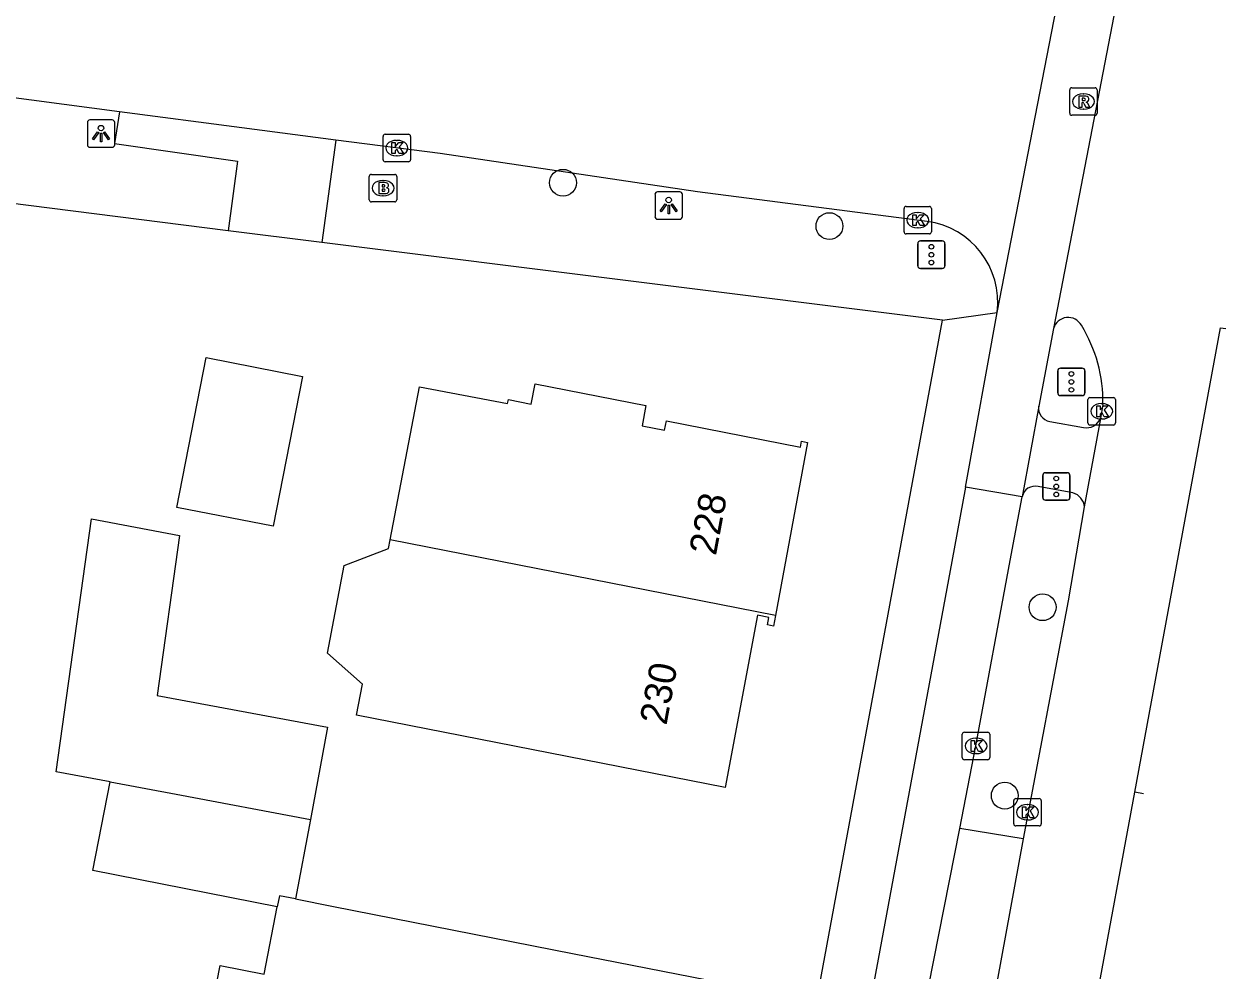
# Model space of a CAD drawing. Extents: x 161258 to 161838, y 380836 to 381727.
# Drawn here: x 161735.93 to 161779.71, y 381300.13 to 381334.61 of the extents above; entities that cross this region are included whole.
import ezdxf

# ---------------------------------------------------------------- set-up
doc = ezdxf.new("R2010")
doc.units = 0
for name, color, linetype in [('IMGEO_Boom', 7, 'Continuous'), ('IMGEO_Brandkraan', 7, 'Continuous'), ('IMGEO_Fietspad_gesloten', 7, 'Continuous'), ('IMGEO_Fietspad_open', 7, 'Continuous'), ('IMGEO_Kolk', 7, 'Continuous'), ('IMGEO_Lichtpunt', 7, 'Continuous'), ('IMGEO_OVBaan_gesloten', 7, 'Continuous'), ('IMGEO_Pand', 7, 'Continuous'), ('IMGEO_Pand_nummerreeks', 7, 'Continuous'), ('IMGEO_Rijbaan_lokaal_open', 7, 'Continuous'), ('IMGEO_Rijbaan_regionaal_gesloten', 7, 'Continuous'), ('IMGEO_Rioolput', 7, 'Continuous'), ('IMGEO_Verkeersregelinstallatiepaal', 7, 'Continuous'), ('IMGEO_Voetpad_open', 7, 'Continuous')]:
    doc.layers.add(name, color=color, linetype=linetype)

msp = doc.modelspace()

# ---------------------------------------------------------------- linework, layer by layer
at = {"layer": 'IMGEO_Boom'}
for centre in [(161755.562, 381328.829), (161765.266, 381327.249), (161773.031, 381313.372), (161771.653, 381306.512)]:
    msp.add_circle(centre, 0.489, dxfattribs=at)
at = {"layer": 'IMGEO_Brandkraan'}
for p, q in [((161748.506, 381328.208), (161748.506, 381329.06)), ((161748.581, 381329.134), (161749.433, 381329.134)), ((161748.994, 381328.914), (161749.019, 381328.914)), ((161749.507, 381329.06), (161749.507, 381328.208)), ((161749.017, 381328.354), (161748.992, 381328.354)), ((161749.433, 381328.134), (161748.581, 381328.134))]:
    msp.add_line(p, q, dxfattribs=at)
for points in [[(161748.506, 381328.208), (161748.506, 381329.06)], [(161748.581, 381329.134), (161749.433, 381329.134)], [(161748.854, 381328.834), (161748.854, 381328.434), (161749.067, 381328.434)], [(161749.085, 381328.834), (161748.854, 381328.834)], [(161749.507, 381329.06), (161749.507, 381328.208)], [(161749.033, 381328.753), (161748.979, 381328.753), (161748.979, 381328.677)], [(161748.979, 381328.677), (161749.032, 381328.677)], [(161749.041, 381328.601), (161748.979, 381328.601), (161748.979, 381328.52)], [(161748.979, 381328.52), (161749.041, 381328.52)], [(161749.433, 381328.134), (161748.581, 381328.134)]]:
    msp.add_lwpolyline(points, dxfattribs=at)
for centre, radius, start, end in [((161748.583, 381329.058), 0.0765, 91.552, 178.448), ((161748.583, 381329.058), 0.0765, 91.552, 178.448), ((161749.089, 381328.689), 0.145, 59.4692, 91.5367), ((161749.114, 381328.736), 0.0922, 285.5137, 58.1501), ((161749.431, 381329.058), 0.0765, 1.552, 88.448), ((161749.431, 381329.058), 0.0765, 1.552, 88.448), ((161749.034, 381328.715), 0.0379, 267.8285, 90.9355), ((161749.042, 381328.56), 0.0404, 269.8759, 90.5077), ((161749.073, 381328.685), 0.251, 268.6676, 293.5347), ((161749.119, 381328.544), 0.105, 301.3115, 78.989), ((161748.583, 381328.21), 0.0765, 181.552, 268.448), ((161748.583, 381328.21), 0.0765, 181.552, 268.448), ((161749.431, 381328.21), 0.0765, 271.552, 358.448), ((161749.431, 381328.21), 0.0765, 271.552, 358.448)]:
    msp.add_arc(centre, radius, start, end, dxfattribs=at)
for centre, major_axis, ratio, start_param, end_param in [((161748.993, 381328.634), (-0.387, 0.002), 0.722429, 4.712389, 7.853982), ((161749.018, 381328.634), (-0.39, 0.002), 0.717154, 1.570796, 4.712389)]:
    msp.add_ellipse(centre, major_axis=major_axis, ratio=ratio, start_param=start_param, end_param=end_param, dxfattribs=at)
at = {"layer": 'IMGEO_Fietspad_gesloten'}
for points in [[(161770.217, 381317.745), (161771.375, 381324.109)], [(161773.43, 381323.525), (161772.887, 381320.696)], [(161772.887, 381320.696), (161772.289, 381317.394)], [(161772.289, 381317.394), (161770.217, 381317.745)]]:
    msp.add_lwpolyline(points, dxfattribs=at)
at = {"layer": 'IMGEO_Fietspad_open'}
for points in [[(161770.217, 381317.745), (161769.724, 381315.032), (161762.12, 381274.018), (161757.67, 381250), (161756.52, 381243.79), (161755.513, 381238.354), (161742.385, 381167.493), (161739.245, 381150.478)], [(161770.018, 381305.316), (161770.601, 381308.32), (161771.852, 381315.075), (161772.289, 381317.394)]]:
    msp.add_lwpolyline(points, dxfattribs=at)
at = {"layer": 'IMGEO_Kolk'}
for p, q in [((161749.007, 381329.667), (161749.007, 381330.519)), ((161749.082, 381330.593), (161749.934, 381330.593)), ((161750.008, 381330.519), (161750.008, 381329.667)), ((161749.495, 381330.373), (161749.52, 381330.373)), ((161749.518, 381329.813), (161749.493, 381329.813)), ((161749.934, 381329.593), (161749.082, 381329.593)), ((161767.982, 381327.041), (161767.982, 381327.893)), ((161768.057, 381327.967), (161768.909, 381327.967)), ((161768.983, 381327.893), (161768.983, 381327.041)), ((161768.47, 381327.747), (161768.495, 381327.747)), ((161768.493, 381327.187), (161768.468, 381327.187)), ((161768.909, 381326.967), (161768.057, 381326.967)), ((161774.681, 381320.081), (161774.681, 381320.933)), ((161774.756, 381321.007), (161775.608, 381321.007)), ((161775.682, 381320.933), (161775.682, 381320.081)), ((161775.169, 381320.787), (161775.194, 381320.787)), ((161775.192, 381320.227), (161775.167, 381320.227)), ((161775.608, 381320.007), (161774.756, 381320.007)), ((161770.105, 381307.894), (161770.105, 381308.746)), ((161770.18, 381308.82), (161771.032, 381308.82)), ((161771.106, 381308.746), (161771.106, 381307.894)), ((161770.593, 381308.6), (161770.618, 381308.6)), ((161771.032, 381307.82), (161770.18, 381307.82)), ((161770.616, 381308.04), (161770.591, 381308.04)), ((161771.98, 381305.48), (161771.98, 381306.332)), ((161772.055, 381306.406), (161772.907, 381306.406)), ((161772.468, 381306.186), (161772.493, 381306.186)), ((161772.981, 381306.332), (161772.981, 381305.48)), ((161772.491, 381305.626), (161772.466, 381305.626)), ((161772.907, 381305.406), (161772.055, 381305.406))]:
    msp.add_line(p, q, dxfattribs=at)
for points in [[(161749.007, 381329.667), (161749.007, 381330.519)], [(161749.082, 381330.593), (161749.934, 381330.593)], [(161750.008, 381330.519), (161750.008, 381329.667)], [(161749.328, 381330.293), (161749.451, 381330.293), (161749.451, 381330.142), (161749.581, 381330.293), (161749.745, 381330.293), (161749.599, 381330.142), (161749.752, 381329.893), (161749.6, 381329.893), (161749.515, 381330.057), (161749.451, 381329.99), (161749.451, 381329.893), (161749.328, 381329.893), (161749.328, 381330.293)], [(161749.934, 381329.593), (161749.082, 381329.593)], [(161767.982, 381327.041), (161767.982, 381327.893)], [(161768.057, 381327.967), (161768.909, 381327.967)], [(161768.983, 381327.893), (161768.983, 381327.041)], [(161768.303, 381327.667), (161768.426, 381327.667), (161768.426, 381327.516), (161768.556, 381327.667), (161768.72, 381327.667), (161768.574, 381327.516), (161768.727, 381327.267), (161768.575, 381327.267), (161768.49, 381327.431), (161768.426, 381327.364), (161768.426, 381327.267), (161768.303, 381327.267), (161768.303, 381327.667)], [(161768.909, 381326.967), (161768.057, 381326.967)], [(161774.681, 381320.081), (161774.681, 381320.933)], [(161774.756, 381321.007), (161775.608, 381321.007)], [(161775.682, 381320.933), (161775.682, 381320.081)], [(161775.002, 381320.707), (161775.125, 381320.707), (161775.125, 381320.556), (161775.255, 381320.707), (161775.419, 381320.707), (161775.273, 381320.556), (161775.426, 381320.307), (161775.274, 381320.307), (161775.189, 381320.471), (161775.125, 381320.404), (161775.125, 381320.307), (161775.002, 381320.307), (161775.002, 381320.707)], [(161775.608, 381320.007), (161774.756, 381320.007)], [(161770.105, 381307.894), (161770.105, 381308.746)], [(161770.18, 381308.82), (161771.032, 381308.82)], [(161771.106, 381308.746), (161771.106, 381307.894)], [(161770.426, 381308.52), (161770.549, 381308.52), (161770.549, 381308.369), (161770.679, 381308.52), (161770.843, 381308.52), (161770.697, 381308.369), (161770.85, 381308.12), (161770.698, 381308.12), (161770.613, 381308.284), (161770.549, 381308.217), (161770.549, 381308.12), (161770.426, 381308.12), (161770.426, 381308.52)], [(161771.032, 381307.82), (161770.18, 381307.82)], [(161771.98, 381305.48), (161771.98, 381306.332)], [(161772.055, 381306.406), (161772.907, 381306.406)], [(161772.301, 381306.106), (161772.424, 381306.106), (161772.424, 381305.955), (161772.554, 381306.106), (161772.718, 381306.106), (161772.572, 381305.955), (161772.725, 381305.706), (161772.573, 381305.706), (161772.488, 381305.87), (161772.424, 381305.803), (161772.424, 381305.706), (161772.301, 381305.706), (161772.301, 381306.106)], [(161772.981, 381306.332), (161772.981, 381305.48)], [(161772.907, 381305.406), (161772.055, 381305.406)]]:
    msp.add_lwpolyline(points, dxfattribs=at)
for centre, start, end in [((161749.084, 381330.517), 91.552, 178.448), ((161749.084, 381330.517), 91.552, 178.448), ((161749.932, 381330.517), 1.552, 88.448), ((161749.932, 381330.517), 1.552, 88.448), ((161749.084, 381329.669), 181.552, 268.448), ((161749.084, 381329.669), 181.552, 268.448), ((161749.932, 381329.669), 271.552, 358.448), ((161749.932, 381329.669), 271.552, 358.448), ((161768.059, 381327.891), 91.552, 178.448), ((161768.059, 381327.891), 91.552, 178.448), ((161768.907, 381327.891), 1.552, 88.448), ((161768.907, 381327.891), 1.552, 88.448), ((161768.059, 381327.043), 181.552, 268.448), ((161768.059, 381327.043), 181.552, 268.448), ((161768.907, 381327.043), 271.552, 358.448), ((161768.907, 381327.043), 271.552, 358.448), ((161774.758, 381320.931), 91.552, 178.448), ((161774.758, 381320.931), 91.552, 178.448), ((161775.606, 381320.931), 1.552, 88.448), ((161775.606, 381320.931), 1.552, 88.448), ((161774.758, 381320.083), 181.552, 268.448), ((161774.758, 381320.083), 181.552, 268.448), ((161775.606, 381320.083), 271.552, 358.448), ((161775.606, 381320.083), 271.552, 358.448), ((161770.182, 381308.744), 91.552, 178.448), ((161770.182, 381308.744), 91.552, 178.448), ((161771.03, 381308.744), 1.552, 88.448), ((161771.03, 381308.744), 1.552, 88.448), ((161770.182, 381307.896), 181.552, 268.448), ((161770.182, 381307.896), 181.552, 268.448), ((161771.03, 381307.896), 271.552, 358.448), ((161771.03, 381307.896), 271.552, 358.448), ((161772.057, 381306.33), 91.552, 178.448), ((161772.057, 381306.33), 91.552, 178.448), ((161772.905, 381306.33), 1.552, 88.448), ((161772.905, 381306.33), 1.552, 88.448), ((161772.057, 381305.482), 181.552, 268.448), ((161772.057, 381305.482), 181.552, 268.448), ((161772.905, 381305.482), 271.552, 358.448), ((161772.905, 381305.482), 271.552, 358.448)]:
    msp.add_arc(centre, 0.0765, start, end, dxfattribs=at)
for centre, major_axis, ratio, start_param, end_param in [((161749.494, 381330.093), (-0.387, 0.002), 0.722429, 4.712389, 7.853982), ((161749.519, 381330.093), (-0.39, 0.002), 0.717154, 1.570796, 4.712389), ((161768.469, 381327.467), (-0.387, 0.002), 0.722429, 4.712389, 7.853982), ((161768.494, 381327.467), (-0.39, 0.002), 0.717154, 1.570796, 4.712389), ((161775.168, 381320.507), (-0.387, 0.002), 0.722429, 4.712389, 7.853982), ((161775.193, 381320.507), (-0.39, 0.002), 0.717154, 1.570796, 4.712389), ((161770.592, 381308.32), (-0.387, 0.002), 0.722429, 4.712389, 7.853982), ((161770.617, 381308.32), (-0.39, 0.002), 0.717154, 1.570796, 4.712389), ((161772.467, 381305.906), (-0.387, 0.002), 0.722429, 4.712389, 7.853982), ((161772.492, 381305.906), (-0.39, 0.002), 0.717154, 1.570796, 4.712389)]:
    msp.add_ellipse(centre, major_axis=major_axis, ratio=ratio, start_param=start_param, end_param=end_param, dxfattribs=at)
at = {"layer": 'IMGEO_Lichtpunt'}
for p, q in [((161738.237, 381331.023), (161738.237, 381330.216)), ((161738.237, 381331.023), (161738.237, 381330.216)), ((161739.139, 381331.118), (161738.331, 381331.118)), ((161739.139, 381331.118), (161738.331, 381331.118)), ((161739.233, 381330.216), (161739.233, 381331.023)), ((161739.233, 381330.216), (161739.233, 381331.023)), ((161738.331, 381330.122), (161739.139, 381330.122)), ((161738.331, 381330.122), (161739.139, 381330.122)), ((161758.913, 381328.402), (161758.913, 381327.595)), ((161758.913, 381328.402), (161758.913, 381327.595)), ((161759.815, 381328.497), (161759.007, 381328.497)), ((161759.815, 381328.497), (161759.007, 381328.497)), ((161759.909, 381327.595), (161759.909, 381328.402)), ((161759.909, 381327.595), (161759.909, 381328.402)), ((161759.007, 381327.501), (161759.815, 381327.501)), ((161759.007, 381327.501), (161759.815, 381327.501))]:
    msp.add_line(p, q, dxfattribs=at)
for points in [[(161738.611, 381330.687), (161738.65, 381330.659), (161738.462, 381330.397), (161738.424, 381330.424), (161738.611, 381330.687)], [(161738.713, 381330.639), (161738.76, 381330.639), (161738.76, 381330.317), (161738.713, 381330.317), (161738.713, 381330.639)], [(161738.823, 381330.659), (161738.861, 381330.686), (161739.048, 381330.424), (161739.009, 381330.396), (161738.823, 381330.659)], [(161759.287, 381328.066), (161759.326, 381328.038), (161759.138, 381327.776), (161759.1, 381327.803), (161759.287, 381328.066)], [(161759.389, 381328.018), (161759.436, 381328.018), (161759.436, 381327.696), (161759.389, 381327.696), (161759.389, 381328.018)], [(161759.499, 381328.038), (161759.537, 381328.065), (161759.724, 381327.803), (161759.685, 381327.775), (161759.499, 381328.038)]]:
    msp.add_lwpolyline(points, dxfattribs=at)
for centre in [(161738.736, 381330.821), (161759.412, 381328.2)]:
    msp.add_circle(centre, 0.0994, dxfattribs=at)
for centre, start, end in [((161738.331, 381331.023), 90, 180), ((161738.331, 381331.023), 90, 180), ((161739.139, 381331.023), 0, 90), ((161739.139, 381331.023), 0, 90), ((161738.331, 381330.216), 180, 270), ((161738.331, 381330.216), 180, 270), ((161739.139, 381330.216), 270, 0), ((161739.139, 381330.216), 270, 360), ((161759.007, 381328.402), 90, 180), ((161759.007, 381328.402), 90, 180), ((161759.815, 381328.402), 0, 90), ((161759.815, 381328.402), 0, 90), ((161759.007, 381327.595), 180, 270), ((161759.007, 381327.595), 180, 270), ((161759.815, 381327.595), 270, 0), ((161759.815, 381327.595), 270, 360)]:
    msp.add_arc(centre, 0.0946, start, end, dxfattribs=at)
at = {"layer": 'IMGEO_OVBaan_gesloten'}
for points in [[(161732.705, 381071.238), (161742.349, 381122.541), (161776.386, 381306.634)], [(161776.704, 381306.578), (161776.386, 381306.634)]]:
    msp.add_lwpolyline(points, dxfattribs=at)
at = {"layer": 'IMGEO_Pand'}
for points in [[(161741.491, 381317.008), (161742.56, 381322.467), (161746.075, 381321.779), (161745.007, 381316.32), (161741.491, 381317.008)], [(161749.267, 381315.826), (161750.335, 381321.403), (161753.546, 381320.788), (161753.574, 381320.934), (161754.408, 381320.771), (161754.552, 381321.505), (161758.584, 381320.712), (161758.439, 381319.975), (161759.263, 381319.814), (161759.33, 381320.156), (161764.207, 381319.203), (161764.249, 381319.418), (161764.464, 381319.375), (161763.296, 381313.076)], [(161739.069, 381307.013), (161737.099, 381307.382), (161738.382, 381316.587), (161741.592, 381315.986), (161740.78, 381310.162), (161746.989, 381309), (161746.362, 381305.647)], [(161763.296, 381313.076), (161763.224, 381312.686), (161763.009, 381312.729), (161763.059, 381313), (161762.641, 381313.078), (161761.474, 381306.803), (161748.044, 381309.442), (161748.26, 381310.571), (161746.984, 381311.699), (161747.594, 381314.886), (161749.207, 381315.512), (161749.267, 381315.826)], [(161763.296, 381313.076), (161749.267, 381315.826)], [(161745.156, 381302.458), (161738.434, 381303.783), (161739.069, 381307.013)], [(161739.069, 381307.013), (161741.466, 381306.564), (161746.362, 381305.647)], [(161746.362, 381305.647), (161745.82, 381302.749)], [(161745.82, 381302.749), (161747.205, 381302.476), (161755.905, 381300.762), (161760.811, 381299.8), (161760.341, 381297.293), (161761.078, 381297.154), (161760.433, 381293.711), (161759.696, 381293.85), (161759.522, 381292.917), (161754.616, 381293.879), (161746.736, 381295.425), (161742.281, 381296.299), (161743.072, 381300.327), (161744.676, 381300.012), (161745.156, 381302.458)], [(161745.82, 381302.749), (161745.236, 381302.864), (161745.156, 381302.458)]]:
    msp.add_lwpolyline(points, dxfattribs=at)
at = {"layer": 'IMGEO_Rijbaan_lokaal_open'}
for points in [[(161771.375, 381324.109), (161774.147, 381338.339)], [(161739.408, 381331.414), (161729.96, 381332.659), (161726.14, 381333.113)], [(161747.288, 381330.383), (161743.86, 381330.828), (161739.408, 381331.414)], [(161768.822, 381327.424), (161760.466, 381328.497), (161751.089, 381329.889), (161747.288, 381330.383)], [(161768.496, 381297.63), (161770.018, 381305.316)], [(161772.327, 381304.942), (161770.018, 381305.316)]]:
    msp.add_lwpolyline(points, dxfattribs=at)
msp.add_arc((161768.417, 381324.472), 2.98, 353.0128, 82.1895, dxfattribs=at)
at = {"layer": 'IMGEO_Rijbaan_regionaal_gesloten'}
for points in [[(161776.826, 381341.153), (161773.43, 381323.525)], [(161776.386, 381306.634), (161779.513, 381323.547), (161779.709, 381323.516)], [(161775.225, 381320.76), (161775.137, 381320.241)], [(161775.137, 381320.241), (161774.55, 381317.025)], [(161774.55, 381317.025), (161773.958, 381313.603), (161772.327, 381304.942)], [(161772.327, 381304.942), (161770.901, 381297.185)]]:
    msp.add_lwpolyline(points, dxfattribs=at)
for centre, radius, start, end in [((161773.959, 381323.375), 0.55, 28.6352, 164.2192), ((161769.967, 381320.876), 5.259, 358.7357, 31.6937)]:
    msp.add_arc(centre, radius, start, end, dxfattribs=at)
at = {"layer": 'IMGEO_Rioolput'}
for p, q in [((161774.091, 381332.286), (161774.943, 381332.286)), ((161774.016, 381331.36), (161774.016, 381332.212)), ((161774.504, 381332.066), (161774.529, 381332.066)), ((161775.017, 381332.212), (161775.017, 381331.36)), ((161774.527, 381331.506), (161774.502, 381331.506)), ((161774.943, 381331.286), (161774.091, 381331.286))]:
    msp.add_line(p, q, dxfattribs=at)
for points in [[(161774.091, 381332.286), (161774.943, 381332.286)], [(161774.016, 381331.36), (161774.016, 381332.212)], [(161774.605, 381331.984), (161774.353, 381331.986), (161774.353, 381331.586)], [(161774.531, 381331.905), (161774.477, 381331.905), (161774.477, 381331.824)], [(161775.017, 381332.212), (161775.017, 381331.36)], [(161774.353, 381331.586), (161774.477, 381331.586), (161774.477, 381331.748), (161774.488, 381331.748)], [(161774.477, 381331.824), (161774.529, 381331.824)], [(161774.535, 381331.719), (161774.606, 381331.586), (161774.746, 381331.586), (161774.681, 381331.712)], [(161774.943, 381331.286), (161774.091, 381331.286)]]:
    msp.add_lwpolyline(points, dxfattribs=at)
for centre, radius, start, end in [((161774.093, 381332.21), 0.0765, 91.552, 178.448), ((161774.093, 381332.21), 0.0765, 91.552, 178.448), ((161774.941, 381332.21), 0.0765, 1.552, 88.448), ((161774.941, 381332.21), 0.0765, 1.552, 88.448), ((161774.513, 381332.013), 0.19, 274.7715, 282.9687), ((161774.537, 381331.809), 0.0964, 77.0061, 93.1865), ((161774.551, 381331.866), 0.0378, 276.6634, 79.6772), ((161774.604, 381331.874), 0.109, 350.3612, 89.416), ((161774.602, 381331.874), 0.112, 277.5842, 350.9817), ((161774.487, 381331.695), 0.0533, 26.0293, 88.6989), ((161774.586, 381331.659), 0.108, 29.5134, 73.7905), ((161774.093, 381331.362), 0.0765, 181.552, 268.448), ((161774.093, 381331.362), 0.0765, 181.552, 268.448), ((161774.941, 381331.362), 0.0765, 271.552, 358.448), ((161774.941, 381331.362), 0.0765, 271.552, 358.448)]:
    msp.add_arc(centre, radius, start, end, dxfattribs=at)
for centre, major_axis, ratio, start_param, end_param in [((161774.503, 381331.786), (-0.387, 0.002), 0.722429, 4.712389, 7.853982), ((161774.528, 381331.786), (-0.39, 0.002), 0.717154, 1.570796, 4.712389)]:
    msp.add_ellipse(centre, major_axis=major_axis, ratio=ratio, start_param=start_param, end_param=end_param, dxfattribs=at)
at = {"layer": 'IMGEO_Verkeersregelinstallatiepaal'}
for p, q in [((161768.483, 381325.81), (161768.483, 381326.61)), ((161768.483, 381326.61), (161768.483, 381325.81)), ((161768.583, 381326.71), (161769.373, 381326.71)), ((161769.373, 381326.71), (161768.583, 381326.71)), ((161769.473, 381326.61), (161769.473, 381325.81)), ((161769.473, 381325.81), (161769.473, 381326.61)), ((161769.373, 381325.71), (161768.583, 381325.71)), ((161768.583, 381325.71), (161769.373, 381325.71)), ((161773.582, 381321.178), (161773.582, 381321.978)), ((161773.582, 381321.978), (161773.582, 381321.178)), ((161773.682, 381322.078), (161774.472, 381322.078)), ((161774.472, 381322.078), (161773.682, 381322.078)), ((161774.572, 381321.978), (161774.572, 381321.178)), ((161774.572, 381321.178), (161774.572, 381321.978)), ((161774.472, 381321.078), (161773.682, 381321.078)), ((161773.682, 381321.078), (161774.472, 381321.078)), ((161773.134, 381318.27), (161773.924, 381318.27)), ((161773.924, 381318.27), (161773.134, 381318.27)), ((161773.034, 381317.37), (161773.034, 381318.17)), ((161773.034, 381318.17), (161773.034, 381317.37)), ((161774.024, 381318.17), (161774.024, 381317.37)), ((161774.024, 381317.37), (161774.024, 381318.17)), ((161773.924, 381317.27), (161773.134, 381317.27)), ((161773.134, 381317.27), (161773.924, 381317.27))]:
    msp.add_line(p, q, dxfattribs=at)
for centre in [(161768.978, 381326.5), (161768.978, 381326.21), (161768.978, 381325.92), (161774.077, 381321.868), (161774.077, 381321.578), (161774.077, 381321.288), (161773.529, 381318.06), (161773.529, 381317.77), (161773.529, 381317.48)]:
    msp.add_circle(centre, 0.085, dxfattribs=at)
for centre, start, end in [((161768.583, 381326.61), 90, 180), ((161768.583, 381326.61), 90, 180), ((161769.373, 381326.61), 0, 90), ((161769.373, 381326.61), 360, 90), ((161768.583, 381325.81), 180, 270), ((161768.583, 381325.81), 180, 270), ((161769.373, 381325.81), 270, 0), ((161769.373, 381325.81), 270, 0), ((161773.682, 381321.978), 90, 180), ((161773.682, 381321.978), 90, 180), ((161774.472, 381321.978), 0, 90), ((161774.472, 381321.978), 360, 90), ((161773.682, 381321.178), 180, 270), ((161773.682, 381321.178), 180, 270), ((161774.472, 381321.178), 270, 0), ((161774.472, 381321.178), 270, 0), ((161773.134, 381318.17), 90, 180), ((161773.134, 381318.17), 90, 180), ((161773.924, 381318.17), 0, 90), ((161773.924, 381318.17), 360, 90), ((161773.134, 381317.37), 180, 270), ((161773.134, 381317.37), 180, 270), ((161773.924, 381317.37), 270, 0), ((161773.924, 381317.37), 270, 0)]:
    msp.add_arc(centre, 0.1, start, end, dxfattribs=at)
at = {"layer": 'IMGEO_Voetpad_open'}
for points in [[(161739.408, 381331.414), (161739.222, 381330.253), (161743.7, 381329.615), (161743.36, 381327.08)], [(161747.288, 381330.383), (161746.772, 381326.654)], [(161743.36, 381327.08), (161725.655, 381329.321)], [(161746.772, 381326.654), (161743.36, 381327.08)], [(161769.385, 381323.827), (161746.772, 381326.654)], [(161769.385, 381323.827), (161771.375, 381324.109)], [(161754.635, 381244.025), (161769.385, 381323.827)], [(161773.293, 381320.135), (161774.523, 381319.919)], [(161774.134, 381317.533), (161772.867, 381317.767)]]:
    msp.add_lwpolyline(points, dxfattribs=at)
for centre, radius, start, end in [((161773.384, 381320.629), 0.502, 172.2867, 259.5004), ((161774.634, 381320.453), 0.545, 258.2055, 337.1423), ((161772.756, 381317.305), 0.476, 76.5117, 169.1589), ((161774.001, 381316.999), 0.55, 2.6726, 75.9553)]:
    msp.add_arc(centre, radius, start, end, dxfattribs=at)

# ---------------------------------------------------------------- texts
at = {"layer": 'IMGEO_Pand_nummerreeks'}
for s, rotation, p in [('228', 79.4978, (161761.131, 381315.226)), ('230', 79.4635, (161759.328, 381309.05))]:
    msp.add_text(s, height=1, rotation=rotation, dxfattribs=at).set_placement(p)

doc.saveas('drawing.dxf')
